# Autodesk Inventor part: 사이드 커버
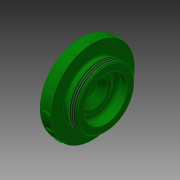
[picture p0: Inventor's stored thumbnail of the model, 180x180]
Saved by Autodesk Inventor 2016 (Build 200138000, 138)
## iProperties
Created: 2016-08
Part Number: 사이드 커버
Material: 스테인리스강
Document SubType Name: Modeling
Designer: mduedu
Density: 8.08 g/cm^3
Appearance: 진녹색
Author: mduedu
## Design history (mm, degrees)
sketch "스케치1"
  geometry: L1 (3, 0)-(10, 0); L2 (4, 24)-(4, 32); L3 (4, 32)-(14, 32); L4 (14, 32)-(14, 22.5); L5 (14, 22.5)-(24, 22.5); L6 (24, 22.5)-(24, 16.5); L7 (16, 11)-(10, 5); L8 (10, 5)-(10, 0); L9 (4, 24)-(0, 21.199); L10 (0, 21.199)-(0, 17.059); L11 (24, 16.5)-(16, 16.5); L12 (16, 16.5)-(16, 11); A1 r 50 centre (-47, 0) between (3, 0) and (0, 17.059); 1 further point
  constraints: 25 end point, 4 parallel, 4 perpendicular, 2 point on circle, 2 point on line, 1 centre point, 1 horizontal, 1 horizontal alignment, 1 vertical
  dimensions: "d2" = 64 diameter of L3 L1; "d3" = 45 diameter of L5 L1; "d5" = 6 distance of L5.end L6.end; "d35" = 48 diameter of L2.start L1; "d36" = 10 distance of L2.end L3.end; "d37" = 24 distance between parallel lines of L6 L10; "d39" = 125 deg angle of L10 L9; "d42" = 10 distance between parallel lines of L6 L4; "d44" = 3 distance of L1.start point (0, 0); "d45" = 50 radius of A1; "d47" = 135 deg angle of L7 L12; "d49" = 22 diameter of L7.start L1; "d50" = 8 distance between parallel lines of L6 L12; "d51" = 6 distance between parallel lines of L12 L8
revolve "회전1" sketch "스케치1" stored, may be unused: angle "d6" = 90 deg
fillet "모깎기1" dims "d7" = 3
sketch "스케치2"
  geometry: L1 (14, -32)-(14, 32) reference; L2 (14, 22.5)-(24, 22.5) reference; L3 (0, 0)-(14, 0); L4 (14, 22.5)-(18.492, 22.5); L5 (18.492, 22.5)-(16.5, 21.35); L6 (16.5, 21.35)-(14, 21.35); L7 (14, 21.35)-(14, 22.5)
  constraints: 10 end point, 1 horizontal, 1 midpoint, 1 parallel, 1 vertical
  dimensions: "d9" = 42.7 diameter of L6 L3; "d31" = 30 deg angle of L2 L5; "d32" = 2.5 distance from line of L1 L5.end
revolve "회전2" sketch "스케치2" stored, may be unused: angle "d10" = 90 deg
fillet "모깎기2" dims "d11" = 3, "d33" = 0.8
feature "스레드1" dims "d12" = 10, "d13" = 0
chamfer "모따기1" distance "d14" = 1; stored, may be unused: second distance "d15" = 2, angle "d16" = 45 deg
node "작업 평면1"
sketch "스케치3"
  geometry: L1 (-8, -1)-(-13, -1); L2 (-13, -1)-(-13, 1); L3 (-13, 1)-(-8, 1); L4 (-8, 1)-(-8, -1); 2 further points
  constraints: 8 end point, 2 parallel, 1 horizontal, 1 horizontal alignment, 1 midpoint, 1 perpendicular
  dimensions: "d18" = 2 distance of L3.end L1.start; "d20" = 5 distance of L1.start L1.end; "d41" = 8 distance from line of point (0, 0) L4
extrude "돌출1" join sketch "스케치3" stored distance "d22" = 10; taper "d23" = 0 deg
fillet "모깎기3" dims "d24" = 1
fillet "모깎기4" dims "d25" = 0.2
node "솔리드1"
pattern_circular "원형 패턴1" dims "d27" = 360 deg
other parameters: "d17" = 32.5
